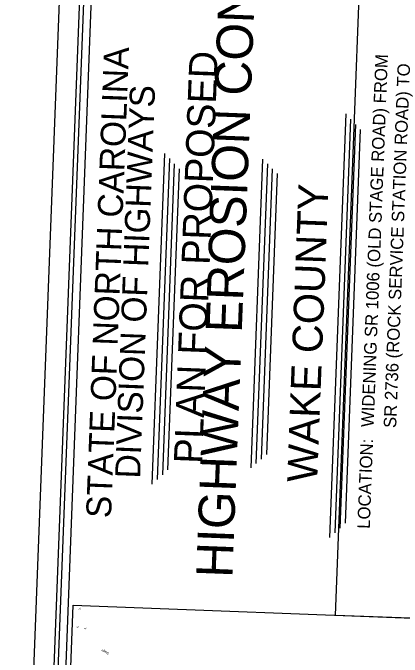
# Model space of a CAD drawing. Extents: x 1654773 to 2116434, y 680831 to 888488.
# Drawn here: x 2094746 to 2096697, y 685073 to 688306 of the extents above; entities that cross this region are included whole.
import ezdxf

# ---------------------------------------------------------------- set-up
doc = ezdxf.new("R2010")
doc.units = 0
for name, color, linetype in [('EC Title Sheet CELL', 7, 'Continuous'), ('Exist Road Secondary Type 51 Label', 7, 'Continuous'), ('Scratch_Level_3', 7, 'Continuous'), ('Sheet Data Field CELL', 7, 'Continuous'), ('Sheet Plot Border Inside CELL', 7, 'Continuous'), ('Sheet Plot Border Outside CELL', 7, 'Continuous'), ('Sheet Title CELL', 7, 'Continuous'), ('Sheet Title Data Points CELL', 7, 'Continuous')]:
    doc.layers.add(name, color=color, linetype=linetype)

msp = doc.modelspace()

# ---------------------------------------------------------------- linework, layer by layer
at = {"layer": 'EC Title Sheet CELL'}
for p, q in [((2094948.2, 683360.1), (2095223.7, 690537.4)), ((2095940.3, 686022), (2095999.7, 687572.4)), ((2095966.3, 686044.3), (2096024.1, 687548.2)), ((2095992.5, 686066.7), (2096048.4, 687523.9)), ((2096018.6, 686089), (2096072.7, 687499.7))]:
    msp.add_line(p, q, dxfattribs=at)
msp.add_lwpolyline([(2095184.2, 690535.2), (2094896.9, 683050)], dxfattribs=at)
at = {"layer": 'Scratch_Level_3'}
for points in [[(2096808.4, 683360), (2096881.4, 685262.6), (2096363.6, 685282.4), (2096507.8, 689043.2), (2096159.7, 689056.5), (2096216.4, 690534.7), (2098809.6, 690435.2), (2098650.1, 686277.9), (2099132, 686259.4), (2099018.8, 683308.3), (2099031.1, 683307.9), (2099030, 683278.9)], [(2094975.9, 683430.3), (2095048.9, 685332.8), (2096881.4, 685262.6), (2096808.4, 683360)]]:
    msp.add_lwpolyline(points, close=True, dxfattribs=at)
at = {"layer": 'Sheet Plot Border Inside CELL'}
msp.add_lwpolyline([(2095168.6, 690692.8), (2094849, 682366.6), (2100144.4, 682163.3), (2100464, 690489.5)], close=True, dxfattribs=at)
at = {"layer": 'Sheet Plot Border Outside CELL'}
msp.add_lwpolyline([(2100242.3, 682094.5), (2100565.2, 690508.2), (2095069.1, 690719.1), (2094746.1, 682305.5)], close=True, dxfattribs=at)
msp.add_lwpolyline([(2100242.3, 682094.5), (2100565.2, 690508.2), (2095069.1, 690719.1), (2094746.1, 682305.5)], close=True, dxfattribs=at)
at = {"layer": 'Sheet Title CELL'}
for p, q in [((2096335.5, 685672.6), (2096417.1, 687798.3)), ((2096361.5, 685696.6), (2096441.2, 687772.4)), ((2096387.6, 685720.5), (2096465.3, 687746.4)), ((2096413.5, 685744.5), (2096489.4, 687720.5)), ((2095445, 685939.9), (2095508.7, 687600.3)), ((2095471, 685963.9), (2095532.9, 687574.3)), ((2095497.1, 685987.8), (2095556.9, 687548.4)), ((2095523.1, 686011.8), (2095581, 687522.5))]:
    msp.add_line(p, q, dxfattribs=at)
at = {"layer": 'Sheet Title Data Points CELL'}
msp.add_line((2096056.7, 687355.3), (2096056.7, 687355.3), dxfattribs=at)

# ---------------------------------------------------------------- texts
at = {"layer": 'EC Title Sheet CELL'}
for s, height, p in [('HIGHWAY EROSION CONTROL', 181.978, (2095846.2, 685469)), ('PLAN FOR PROPOSED', 141.524, (2095694.3, 686041.4))]:
    msp.add_text(s, height=height, rotation=87.802, dxfattribs=at).set_placement(p)
at = {"layer": 'Exist Road Secondary Type 51 Label'}
for s, rotation, p in [('3.', 87.8037, (2095086, 685309)), ('3.', 87.8037, (2095086, 685309)), ('5.', 87.8037, (2095076.4, 685217.7)), ('5.', 87.8037, (2095076.4, 685217.7)), ('4.', 87.8037, (2095113.7, 685212)), ('4.', 87.8037, (2095113.7, 685212)), ('Stage', 154.833, (2095229.1, 685095.1)), ('Stage', 154.833, (2095229.1, 685095.1))]:
    msp.add_text(s, height=11.13, rotation=rotation, dxfattribs=at).set_placement(p)
at = {"layer": 'Sheet Data Field CELL'}
for s, height, p in [('WIDENING SR 1006 (OLD STAGE ROAD) FROM', 62.69, (2096554.7, 686226.2)), ('SR 2736 (ROCK SERVICE STATION ROAD) TO', 62.69, (2096667.5, 686221.8)), ('WAKE COUNTY', 150.455, (2096271.3, 685947.9))]:
    msp.add_text(s, height=height, rotation=87.802, dxfattribs=at).set_placement(p)
at = {"layer": 'Sheet Title CELL'}
for s, height, p in [('STATE OF NORTH CAROLINA', 125.378, (2095238, 685768.9)), ('DIVISION OF HIGHWAYS', 125.378, (2095383.6, 685967.7)), ('LOCATION: ', 62.69, (2096535.2, 685715.9))]:
    msp.add_text(s, height=height, rotation=87.802, dxfattribs=at).set_placement(p)

doc.saveas('drawing.dxf')
